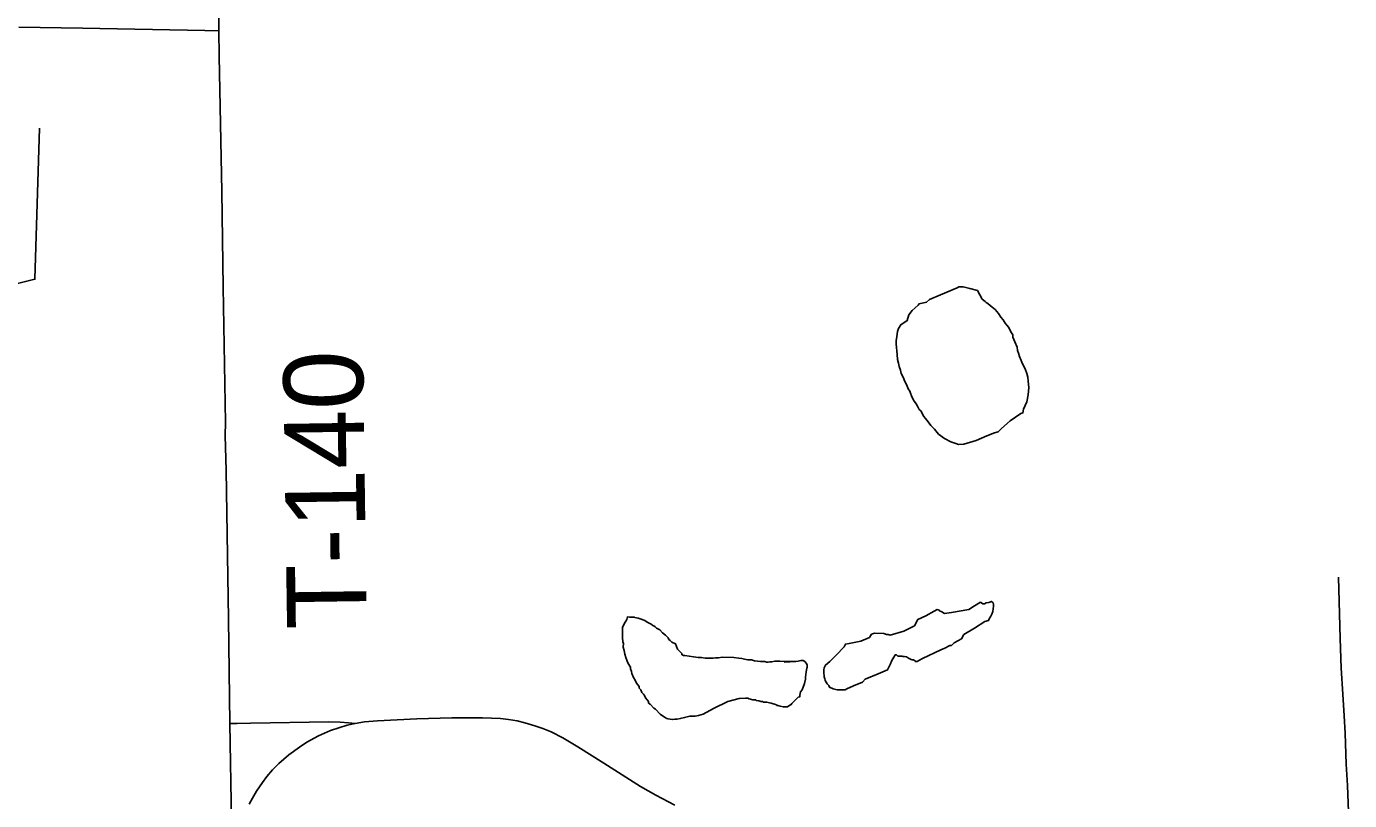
# Model space of a CAD drawing. Extents: x -12 to 34, y 0 to 22.
# Drawn here: x 5.999 to 6.941, y 16.556 to 17.107 of the extents above; entities that cross this region are included whole.
import ezdxf

# ---------------------------------------------------------------- set-up
doc = ezdxf.new("R2010")
doc.units = 0
for name, color, linetype in [('GM_X_County_Road_Text', 7, 'Continuous'), ('GM_X_Major_Lake', 7, 'Continuous'), ('GM_X_Major_River', 7, 'Continuous'), ('GM_X_Minor_Lake', 7, 'Continuous'), ('GM_X_Township', 7, 'Continuous')]:
    doc.layers.add(name, color=color, linetype=linetype)

msp = doc.modelspace()

# ---------------------------------------------------------------- linework, layer by layer
at = {"layer": 'GM_X_Major_Lake'}
msp.add_lwpolyline([(6.46038, 16.55268), (6.44663, 16.55981), (6.43588, 16.56598), (6.40971, 16.58272), (6.39128, 16.59435), (6.38049, 16.60062), (6.37211, 16.60486), (6.36632, 16.60726), (6.36051, 16.60922), (6.35347, 16.61139), (6.34806, 16.61274), (6.34174, 16.61382), (6.33606, 16.61445), (6.32331, 16.61487), (6.30151, 16.61487), (6.27665, 16.61414), (6.24868, 16.61283), (6.23934, 16.61196), (6.23255, 16.61086), (6.22702, 16.60964), (6.221, 16.6079), (6.21509, 16.60579), (6.20648, 16.602), (6.19822, 16.5975), (6.19296, 16.5941), (6.18541, 16.58849), (6.17832, 16.58231), (6.1739, 16.57784), (6.16984, 16.57305), (6.16671, 16.56884), (6.16246, 16.56267), (6.15955, 16.55778), (6.15713, 16.55335)], dxfattribs=at)
at = {"layer": 'GM_X_Major_River'}
for points in [[(6.13555, 17.10387), (6.1355, 17.12364), (6.13452, 17.181), (6.13328, 17.23375), (6.13281, 17.25856), (6.13225, 17.28958), (6.12985, 17.40132), (6.12601, 17.56894), (6.12415, 17.64034), (6.12309, 17.68378), (6.11921, 17.84888), (6.11878, 17.85991), (6.11865, 17.86316)], [(6.13555, 17.10387), (6.12567, 17.10414), (6.03855, 17.10592), (5.9933, 17.10651)], [(6.14348, 16.61083), (6.14255, 16.68536), (6.14083, 16.79096), (6.14019, 16.8158), (6.14023, 16.8251), (6.13876, 16.92139), (6.13762, 16.9897), (6.13581, 17.08598), (6.13555, 17.10387)], [(6.94066, 16.53116), (6.94056, 16.53505), (6.93987, 16.54793), (6.93917, 16.56672), (6.9383, 16.58203), (6.93752, 16.60404), (6.93693, 16.61637), (6.93587, 16.6318), (6.93468, 16.65032), (6.93394, 16.6713), (6.93324, 16.69775), (6.93278, 16.7151)], [(6.14348, 16.61083), (6.14873, 16.61095), (6.15813, 16.61107), (6.21386, 16.61218), (6.22195, 16.61183), (6.22794, 16.61136), (6.23255, 16.61086)], [(6.14543, 16.50898), (6.14466, 16.54122), (6.14348, 16.61083)]]:
    msp.add_lwpolyline(points, dxfattribs=at)
at = {"layer": 'GM_X_Minor_Lake'}
for points in [[(6.00784, 17.0347), (6.00459, 16.92713), (5.94884, 16.91318), (5.9497, 16.44378), (5.84644, 16.44064), (6.11255, 16.44872)], [(6.67901, 16.91288), (6.67569, 16.91901), (6.67041, 16.9206), (6.66549, 16.92181), (6.66246, 16.92185), (6.66131, 16.92111), (6.64948, 16.91596), (6.64147, 16.91266), (6.63955, 16.91079), (6.63422, 16.90972), (6.63345, 16.90859), (6.62922, 16.90486), (6.6269, 16.90185), (6.6257, 16.89769), (6.62111, 16.89472), (6.61955, 16.89208), (6.61876, 16.88982), (6.61833, 16.8864), (6.61791, 16.88337), (6.61787, 16.88109), (6.61852, 16.87349), (6.61885, 16.87007), (6.61957, 16.8674), (6.61991, 16.86511), (6.62101, 16.86244), (6.62136, 16.86015), (6.62283, 16.85747), (6.62393, 16.85442), (6.6254, 16.85174), (6.6265, 16.84907), (6.62762, 16.84753), (6.62797, 16.84601), (6.6287, 16.8441), (6.63017, 16.84104), (6.63203, 16.83836), (6.63315, 16.83682), (6.63425, 16.83453), (6.63537, 16.83337), (6.63759, 16.82954), (6.6387, 16.82801), (6.64057, 16.8257), (6.64242, 16.82302), (6.64504, 16.82032), (6.64802, 16.81686)], [(6.67901, 16.91288), (6.67569, 16.91901), (6.67041, 16.9206), (6.66549, 16.92181), (6.66246, 16.92185), (6.66131, 16.92111), (6.64948, 16.91596), (6.64147, 16.91266), (6.63955, 16.91079), (6.63422, 16.90972), (6.63345, 16.90859), (6.62922, 16.90486), (6.6269, 16.90185), (6.6257, 16.89769), (6.62111, 16.89472), (6.61955, 16.89208), (6.61876, 16.88982), (6.61833, 16.8864), (6.61791, 16.88337), (6.61787, 16.88109), (6.61852, 16.87349), (6.61885, 16.87007), (6.61957, 16.8674), (6.61991, 16.86511), (6.62101, 16.86244), (6.62136, 16.86015), (6.62283, 16.85747), (6.62393, 16.85442), (6.6254, 16.85174), (6.6265, 16.84907), (6.62762, 16.84753), (6.62797, 16.84601), (6.6287, 16.8441), (6.63017, 16.84104), (6.63203, 16.83836), (6.63315, 16.83682), (6.63425, 16.83453), (6.63537, 16.83337), (6.63759, 16.82954), (6.6387, 16.82801), (6.64057, 16.8257), (6.64242, 16.82302), (6.64504, 16.82032), (6.64802, 16.81686), (6.65215, 16.81376), (6.65666, 16.81142), (6.66044, 16.81023), (6.66232, 16.80944), (6.66612, 16.80977), (6.67487, 16.8123), (6.68251, 16.81561), (6.68785, 16.81782), (6.69052, 16.81854), (6.69282, 16.82078), (6.69897, 16.82639), (6.70663, 16.8316), (6.70816, 16.83196), (6.70857, 16.83461), (6.71093, 16.83989), (6.71176, 16.84482), (6.71222, 16.85013), (6.7119, 16.85469), (6.71156, 16.85735), (6.71084, 16.86002), (6.70976, 16.86346), (6.70791, 16.8669), (6.70681, 16.86919), (6.70572, 16.87225), (6.70499, 16.87454), (6.70426, 16.87645), (6.70391, 16.87873), (6.70246, 16.88255), (6.70099, 16.88599), (6.70101, 16.88751), (6.69953, 16.8898), (6.69806, 16.89286), (6.69656, 16.8944), (6.69545, 16.89594), (6.69397, 16.89824), (6.69248, 16.90016), (6.69062, 16.90284), (6.68838, 16.90553), (6.68501, 16.90824), (6.68314, 16.90979), (6.68201, 16.91056), (6.68127, 16.91133), (6.67901, 16.91288)], [(6.64802, 16.81686), (6.65215, 16.81376), (6.65666, 16.81142), (6.66044, 16.81023), (6.66232, 16.80944), (6.66612, 16.80977), (6.67487, 16.8123), (6.68251, 16.81561), (6.68785, 16.81782), (6.69052, 16.81854), (6.69282, 16.82078), (6.69897, 16.82639), (6.70663, 16.8316), (6.70816, 16.83196), (6.70857, 16.83461), (6.71093, 16.83989), (6.71176, 16.84482), (6.71222, 16.85013), (6.7119, 16.85469), (6.71156, 16.85735), (6.71084, 16.86002), (6.70976, 16.86346), (6.70791, 16.8669), (6.70681, 16.86919), (6.70572, 16.87225), (6.70499, 16.87454), (6.70426, 16.87645), (6.70391, 16.87873), (6.70246, 16.88255), (6.70099, 16.88599), (6.70101, 16.88751), (6.69953, 16.8898), (6.69806, 16.89286), (6.69656, 16.8944), (6.69545, 16.89594), (6.69397, 16.89824), (6.69248, 16.90016), (6.69062, 16.90284), (6.68838, 16.90553), (6.68501, 16.90824), (6.68314, 16.90979), (6.68201, 16.91056), (6.68127, 16.91133), (6.67901, 16.91288)], [(6.67795, 16.69717), (6.67352, 16.69459), (6.66969, 16.69199), (6.65714, 16.68989), (6.6522, 16.6892), (6.65032, 16.69036), (6.64882, 16.69115), (6.64845, 16.69153), (6.64694, 16.69193), (6.64502, 16.69082), (6.63891, 16.68749), (6.63318, 16.68491), (6.63084, 16.68039), (6.6232, 16.6767), (6.61368, 16.6738), (6.61217, 16.6742), (6.61103, 16.67422), (6.60915, 16.675), (6.60232, 16.6751), (6.60041, 16.67436), (6.59886, 16.67211), (6.59276, 16.66954), (6.58439, 16.66776), (6.58173, 16.66741), (6.58094, 16.66553), (6.57517, 16.65953), (6.57055, 16.65504), (6.56748, 16.65243), (6.56669, 16.65054), (6.56629, 16.64903), (6.56627, 16.64751), (6.5666, 16.64408), (6.56695, 16.64256), (6.56732, 16.64179), (6.56732, 16.64142), (6.5688, 16.63912), (6.56992, 16.63796), (6.57028, 16.63682), (6.57292, 16.63564), (6.57594, 16.63484), (6.58163, 16.63476), (6.58278, 16.6355), (6.58736, 16.63771), (6.59384, 16.64028), (6.59577, 16.64253), (6.60493, 16.6462), (6.6118, 16.64914), (6.61258, 16.65103), (6.61375, 16.65329), (6.61454, 16.65518), (6.61726, 16.6597), (6.61802, 16.65968), (6.61915, 16.65891), (6.6218, 16.65887), (6.62255, 16.65848), (6.62369, 16.65847), (6.62521, 16.65844), (6.6267, 16.65728), (6.62859, 16.6565), (6.62934, 16.65611), (6.6301, 16.65609), (6.63161, 16.65531), (6.6316, 16.65493), (6.63274, 16.65492), (6.63389, 16.65566), (6.63656, 16.65714), (6.64955, 16.66341), (6.6526, 16.66451), (6.65604, 16.66636), (6.65717, 16.66634), (6.6591, 16.66822), (6.66445, 16.67118), (6.66601, 16.67419), (6.67366, 16.67864), (6.68094, 16.68348), (6.6836, 16.6842), (6.684, 16.68533), (6.68516, 16.68721), (6.68594, 16.68872), (6.68673, 16.69061), (6.68717, 16.6944), (6.68718, 16.69554), (6.68682, 16.69668), (6.6857, 16.69784), (6.68379, 16.69711), (6.68189, 16.69676), (6.68074, 16.69601), (6.67961, 16.69603), (6.67795, 16.69717)], [(6.67795, 16.69717), (6.67352, 16.69459), (6.66969, 16.69199), (6.65714, 16.68989), (6.6522, 16.6892), (6.65032, 16.69036), (6.64882, 16.69115), (6.64845, 16.69153), (6.64694, 16.69193), (6.64502, 16.69082), (6.63891, 16.68749), (6.63318, 16.68491), (6.63084, 16.68039), (6.6232, 16.6767), (6.61368, 16.6738), (6.61217, 16.6742), (6.61103, 16.67422), (6.60915, 16.675), (6.60232, 16.6751), (6.60041, 16.67436), (6.59886, 16.67211), (6.59276, 16.66954), (6.58439, 16.66776), (6.58173, 16.66741), (6.58094, 16.66553), (6.57517, 16.65953), (6.57055, 16.65504), (6.56748, 16.65243), (6.56669, 16.65054), (6.56629, 16.64903), (6.56627, 16.64751), (6.5666, 16.64408), (6.56695, 16.64256), (6.56732, 16.64179), (6.56732, 16.64142), (6.5688, 16.63912), (6.56992, 16.63796), (6.57028, 16.63682), (6.57292, 16.63564), (6.57594, 16.63484), (6.58163, 16.63476), (6.58278, 16.6355), (6.58736, 16.63771), (6.59384, 16.64028), (6.59577, 16.64253)], [(6.59577, 16.64253), (6.60493, 16.6462), (6.6118, 16.64914), (6.61258, 16.65103), (6.61375, 16.65329), (6.61454, 16.65518), (6.61726, 16.6597), (6.61802, 16.65968), (6.61915, 16.65891), (6.6218, 16.65887), (6.62255, 16.65848), (6.62369, 16.65847), (6.62521, 16.65844), (6.6267, 16.65728), (6.62859, 16.6565), (6.62934, 16.65611), (6.6301, 16.65609), (6.63161, 16.65531), (6.6316, 16.65493), (6.63274, 16.65492), (6.63389, 16.65566), (6.63656, 16.65714), (6.64955, 16.66341), (6.6526, 16.66451), (6.65604, 16.66636), (6.65717, 16.66634), (6.6591, 16.66822), (6.66445, 16.67118), (6.66601, 16.67419), (6.67366, 16.67864), (6.68094, 16.68348), (6.6836, 16.6842), (6.684, 16.68533), (6.68516, 16.68721), (6.68594, 16.68872), (6.68673, 16.69061), (6.68717, 16.6944), (6.68718, 16.69554), (6.68682, 16.69668), (6.6857, 16.69784), (6.68379, 16.69711), (6.68189, 16.69676), (6.68074, 16.69601), (6.67961, 16.69603), (6.67795, 16.69717)], [(6.54628, 16.65501), (6.53491, 16.65517), (6.5315, 16.65522), (6.52922, 16.65487), (6.52808, 16.65489), (6.52656, 16.65453), (6.52542, 16.65454), (6.52429, 16.65494), (6.52125, 16.65498), (6.51709, 16.65542), (6.51483, 16.65621), (6.51217, 16.65625), (6.5099, 16.65666), (6.50801, 16.65707), (6.50574, 16.65748), (6.50234, 16.65791), (6.494, 16.65803), (6.49134, 16.65769), (6.48944, 16.65771), (6.48754, 16.65736), (6.48185, 16.65744), (6.47921, 16.65786), (6.47693, 16.65789), (6.47352, 16.65832), (6.46747, 16.65917), (6.46633, 16.65918), (6.46521, 16.65996), (6.46522, 16.66072), (6.46223, 16.6638), (6.46077, 16.66762), (6.45813, 16.66879), (6.45701, 16.66995), (6.45588, 16.67072), (6.45552, 16.67187), (6.45366, 16.67379), (6.4514, 16.67534), (6.44954, 16.67765), (6.44728, 16.67882), (6.44616, 16.6796), (6.44541, 16.68037), (6.44466, 16.68076), (6.44353, 16.68153), (6.44052, 16.68309), (6.43902, 16.68426), (6.43563, 16.68544), (6.43412, 16.68584), (6.43185, 16.68626), (6.43147, 16.68664), (6.42806, 16.68669), (6.42655, 16.68671), (6.42614, 16.68482), (6.4242, 16.68181), (6.42302, 16.67917), (6.4229, 16.67119), (6.42327, 16.67005), (6.42325, 16.66891), (6.42361, 16.66776), (6.42357, 16.66511), (6.4243, 16.66282), (6.42463, 16.66015), (6.42536, 16.65786), (6.42609, 16.65596), (6.42645, 16.65443), (6.42756, 16.6529), (6.4283, 16.65175), (6.42867, 16.65098), (6.42866, 16.64984), (6.42938, 16.64793), (6.42974, 16.64641), (6.43084, 16.64374), (6.43195, 16.64182), (6.43305, 16.63953), (6.43491, 16.63722), (6.4349, 16.63608), (6.43602, 16.63493), (6.43675, 16.63302), (6.43787, 16.63186), (6.43861, 16.63071), (6.43935, 16.62918), (6.44046, 16.62765), (6.44158, 16.62649), (6.44156, 16.62536), (6.44269, 16.62458), (6.44531, 16.62188), (6.44643, 16.62111), (6.44979, 16.61764), (6.45279, 16.61532), (6.45468, 16.61453), (6.45543, 16.61414), (6.45846, 16.61372), (6.46036, 16.61407), (6.46187, 16.61405), (6.46416, 16.6144), (6.4672, 16.61512), (6.47101, 16.6162), (6.4748, 16.61615)], [(6.53814, 16.65463), (6.54628, 16.65501), (6.53491, 16.65517), (6.5315, 16.65522), (6.52922, 16.65487), (6.52808, 16.65489), (6.52656, 16.65453), (6.52542, 16.65454), (6.52429, 16.65494), (6.52125, 16.65498), (6.51709, 16.65542), (6.51483, 16.65621), (6.51217, 16.65625), (6.5099, 16.65666), (6.50801, 16.65707), (6.50574, 16.65748), (6.50234, 16.65791), (6.494, 16.65803), (6.49134, 16.65769), (6.48944, 16.65771), (6.48754, 16.65736), (6.48185, 16.65744), (6.47921, 16.65786), (6.47693, 16.65789), (6.47352, 16.65832), (6.46747, 16.65917), (6.46633, 16.65918), (6.46521, 16.65996), (6.46522, 16.66072), (6.46223, 16.6638), (6.46077, 16.66762), (6.45813, 16.66879), (6.45701, 16.66995), (6.45588, 16.67072), (6.45552, 16.67187), (6.45366, 16.67379), (6.4514, 16.67534), (6.44954, 16.67765), (6.44728, 16.67882), (6.44616, 16.6796), (6.44541, 16.68037), (6.44466, 16.68076), (6.44353, 16.68153), (6.44052, 16.68309), (6.43902, 16.68426), (6.43563, 16.68544), (6.43412, 16.68584), (6.43185, 16.68626), (6.43147, 16.68664), (6.42806, 16.68669), (6.42655, 16.68671), (6.42614, 16.68482), (6.4242, 16.68181), (6.42302, 16.67917), (6.4229, 16.67119), (6.42327, 16.67005), (6.42325, 16.66891), (6.42361, 16.66776), (6.42357, 16.66511), (6.4243, 16.66282), (6.42463, 16.66015), (6.42536, 16.65786), (6.42609, 16.65596), (6.42645, 16.65443), (6.42756, 16.6529), (6.4283, 16.65175), (6.42867, 16.65098), (6.42866, 16.64984), (6.42938, 16.64793), (6.42974, 16.64641), (6.43084, 16.64374), (6.43195, 16.64182), (6.43305, 16.63953), (6.43491, 16.63722), (6.4349, 16.63608), (6.43602, 16.63493), (6.43675, 16.63302), (6.43787, 16.63186), (6.43861, 16.63071), (6.43935, 16.62918), (6.44046, 16.62765), (6.44158, 16.62649), (6.44156, 16.62536), (6.44269, 16.62458), (6.44531, 16.62188), (6.44643, 16.62111), (6.44979, 16.61764), (6.45279, 16.61532), (6.45468, 16.61453), (6.45543, 16.61414), (6.45846, 16.61372), (6.46036, 16.61407), (6.46187, 16.61405), (6.46416, 16.6144), (6.4672, 16.61512), (6.47101, 16.6162), (6.4748, 16.61615)], [(6.4748, 16.61615), (6.47708, 16.6165), (6.48051, 16.61758), (6.48777, 16.62166), (6.49808, 16.62645), (6.50608, 16.62861), (6.51063, 16.62893), (6.51215, 16.62891), (6.51328, 16.62851), (6.51592, 16.62772), (6.51782, 16.62769), (6.51819, 16.6273), (6.52008, 16.6269), (6.52159, 16.6265), (6.52273, 16.62648), (6.52348, 16.62609), (6.52576, 16.62606), (6.52765, 16.62565), (6.52878, 16.62526), (6.53255, 16.62406), (6.53293, 16.62368), (6.53369, 16.62367), (6.5352, 16.62326), (6.53746, 16.62285), (6.5405, 16.62281), (6.54203, 16.62393), (6.54317, 16.62429), (6.54356, 16.62504), (6.54818, 16.62954), (6.54932, 16.6299), (6.54934, 16.63104), (6.54975, 16.63331), (6.55091, 16.63481), (6.5525, 16.63935), (6.5533, 16.64238), (6.55332, 16.64389), (6.55376, 16.64768), (6.55418, 16.65034), (6.55456, 16.65071), (6.55459, 16.65261), (6.55385, 16.65376), (6.55273, 16.65491), (6.5516, 16.65569), (6.55008, 16.65571), (6.54818, 16.65536), (6.54628, 16.65501)]]:
    msp.add_lwpolyline(points, dxfattribs=at)
at = {"layer": 'GM_X_Township'}
msp.add_lwpolyline([(6.46038, 16.55268), (6.44663, 16.55981), (6.43588, 16.56598), (6.40971, 16.58272), (6.39128, 16.59435), (6.38049, 16.60062), (6.37211, 16.60486), (6.36632, 16.60726), (6.36051, 16.60922), (6.35347, 16.61139), (6.34806, 16.61274), (6.34174, 16.61382), (6.33606, 16.61445), (6.32331, 16.61487), (6.30151, 16.61487), (6.27665, 16.61414), (6.24868, 16.61283), (6.23934, 16.61196), (6.23255, 16.61086), (6.22702, 16.60964), (6.221, 16.6079), (6.21509, 16.60579), (6.20648, 16.602), (6.19822, 16.5975), (6.19296, 16.5941), (6.18541, 16.58849), (6.17832, 16.58231), (6.1739, 16.57784), (6.16984, 16.57305), (6.16671, 16.56884), (6.16246, 16.56267), (6.15955, 16.55778), (6.15713, 16.55335)], dxfattribs=at)

# ---------------------------------------------------------------- texts
at = {"layer": 'GM_X_County_Road_Text'}
msp.add_text('T-140', height=0.056818, rotation=90.84525, dxfattribs=at).set_placement((6.24102, 16.67838))

doc.saveas('drawing.dxf')
